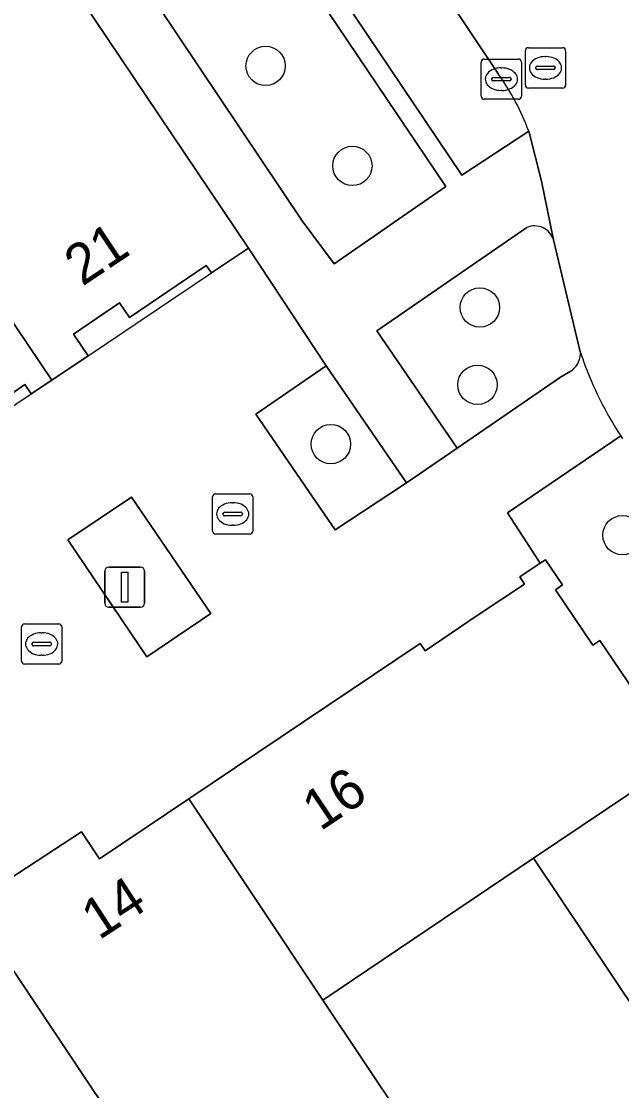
# Model space of a CAD drawing. Extents: x 158793 to 159888, y 384317 to 385256.
# Drawn here: x 159132.82 to 159147.74, y 384807.77 to 384834.32 of the extents above; entities that cross this region are included whole.
import ezdxf

# ---------------------------------------------------------------- set-up
doc = ezdxf.new("R2010")
doc.units = 0
for name, color, linetype in [('IMGEO_Boom', 7, 'Continuous'), ('IMGEO_Erf', 7, 'Continuous'), ('IMGEO_Groenvoorziening', 7, 'Continuous'), ('IMGEO_Kolk', 7, 'Continuous'), ('IMGEO_Lichtmast', 7, 'Continuous'), ('IMGEO_Pand', 7, 'Continuous'), ('IMGEO_Pand_nummerreeks', 7, 'Continuous'), ('IMGEO_Pand_overbouw', 7, 'Continuous'), ('IMGEO_Parkeervlak_open', 7, 'Continuous'), ('IMGEO_Rijbaan_lokaal_open', 7, 'Continuous'), ('IMGEO_Rioolput', 7, 'Continuous'), ('IMGEO_Voetpad_open', 7, 'Continuous')]:
    doc.layers.add(name, color=color, linetype=linetype)

msp = doc.modelspace()

# ---------------------------------------------------------------- linework, layer by layer
at = {"layer": 'IMGEO_Boom'}
for centre in [(159138.893, 384833.21), (159141.048, 384830.727), (159144.217, 384827.212), (159144.156, 384825.292), (159140.515, 384823.82), (159147.761, 384821.559)]:
    msp.add_circle(centre, 0.489, dxfattribs=at)
at = {"layer": 'IMGEO_Erf'}
msp.add_lwpolyline([(159152.783, 384802.742), (159145.552, 384813.536), (159140.318, 384810.016), (159142.302, 384807.041)], dxfattribs=at)
at = {"layer": 'IMGEO_Groenvoorziening'}
for points in [[(159137.509, 384838.918), (159134.663, 384837.03), (159139.797, 384829.364), (159140.593, 384828.294), (159143.37, 384830.219)], [(159140.623, 384821.689), (159142.395, 384822.861), (159140.397, 384825.767), (159138.651, 384824.567), (159139.859, 384822.803)], [(159135.556, 384822.504), (159133.976, 384821.445), (159135.939, 384818.54), (159137.533, 384819.611)]]:
    msp.add_lwpolyline(points, close=True, dxfattribs=at)
for points in [[(159145.384, 384829.198), (159141.656, 384826.635), (159143.651, 384823.723), (159146.223, 384825.482), (159146.515, 384825.659)], [(159146.713, 384826.113), (159146.047, 384828.889)], [(159147.762, 384823.956), (159147.717, 384824.025), (159144.902, 384822.115), (159145.269, 384821.55), (159145.717, 384820.861), (159145.851, 384820.95), (159146.271, 384820.323), (159146.093, 384820.203), (159147.02, 384818.826), (159147.199, 384818.944), (159149.203, 384815.99), (159145.552, 384813.536), (159152.783, 384802.742), (159156.787, 384796.766), (159156.976, 384796.89), (159158.254, 384797.753), (159158.435, 384797.871)]]:
    msp.add_lwpolyline(points, dxfattribs=at)
for centre, radius, start, end in [((159145.58, 384828.752), 0.487, 16.3046, 113.7184), ((159146.177, 384826.077), 0.538, 309.0031, 3.8706)]:
    msp.add_arc(centre, radius, start, end, dxfattribs=at)
at = {"layer": 'IMGEO_Kolk'}
for p, q in [((159144.326, 384833.382), (159145.178, 384833.382)), ((159144.251, 384832.456), (159144.251, 384833.308)), ((159144.739, 384833.162), (159144.764, 384833.162)), ((159145.252, 384833.308), (159145.252, 384832.456)), ((159144.51, 384832.876), (159144.51, 384832.888)), ((159144.948, 384832.839), (159144.55, 384832.839)), ((159144.553, 384832.925), (159144.951, 384832.925)), ((159144.994, 384832.888), (159144.994, 384832.876)), ((159144.762, 384832.602), (159144.737, 384832.602)), ((159145.178, 384832.382), (159144.326, 384832.382)), ((159137.573, 384821.658), (159137.573, 384822.51)), ((159137.648, 384822.584), (159138.5, 384822.584)), ((159138.574, 384822.51), (159138.574, 384821.658)), ((159138.061, 384822.364), (159138.086, 384822.364)), ((159137.832, 384822.078), (159137.832, 384822.09)), ((159138.27, 384822.041), (159137.872, 384822.041)), ((159137.875, 384822.127), (159138.273, 384822.127)), ((159138.316, 384822.09), (159138.316, 384822.078)), ((159138.084, 384821.804), (159138.059, 384821.804)), ((159138.5, 384821.584), (159137.648, 384821.584)), ((159132.901, 384819.356), (159133.753, 384819.356)), ((159132.826, 384818.43), (159132.826, 384819.282)), ((159133.314, 384819.136), (159133.339, 384819.136)), ((159133.827, 384819.282), (159133.827, 384818.43)), ((159133.085, 384818.85), (159133.085, 384818.862)), ((159133.523, 384818.813), (159133.125, 384818.813)), ((159133.128, 384818.899), (159133.526, 384818.899)), ((159133.569, 384818.862), (159133.569, 384818.85)), ((159133.337, 384818.576), (159133.312, 384818.576)), ((159133.753, 384818.356), (159132.901, 384818.356))]:
    msp.add_line(p, q, dxfattribs=at)
for points in [[(159144.326, 384833.382), (159145.178, 384833.382)], [(159144.251, 384832.456), (159144.251, 384833.308)], [(159145.252, 384833.308), (159145.252, 384832.456)], [(159145.178, 384832.382), (159144.326, 384832.382)], [(159137.573, 384821.658), (159137.573, 384822.51)], [(159137.648, 384822.584), (159138.5, 384822.584)], [(159138.574, 384822.51), (159138.574, 384821.658)], [(159138.5, 384821.584), (159137.648, 384821.584)], [(159132.901, 384819.356), (159133.753, 384819.356)], [(159132.826, 384818.43), (159132.826, 384819.282)], [(159133.827, 384819.282), (159133.827, 384818.43)], [(159133.753, 384818.356), (159132.901, 384818.356)]]:
    msp.add_lwpolyline(points, dxfattribs=at)
for centre, radius, start, end in [((159144.328, 384833.306), 0.0765, 91.552, 178.448), ((159144.328, 384833.306), 0.0765, 91.552, 178.448), ((159145.176, 384833.306), 0.0765, 1.552, 88.448), ((159145.176, 384833.306), 0.0765, 1.552, 88.448), ((159144.55, 384832.885), 0.0403, 85.8775, 175.7526), ((159144.547, 384832.875), 0.0366, 178.938, 274.7102), ((159144.951, 384832.882), 0.043, 264.8664, 352.4533), ((159144.955, 384832.887), 0.0386, 1.7309, 96.639), ((159144.328, 384832.458), 0.0765, 181.552, 268.448), ((159144.328, 384832.458), 0.0765, 181.552, 268.448), ((159145.176, 384832.458), 0.0765, 271.552, 358.448), ((159145.176, 384832.458), 0.0765, 271.552, 358.448), ((159137.65, 384822.508), 0.0765, 91.552, 178.448), ((159137.65, 384822.508), 0.0765, 91.552, 178.448), ((159138.498, 384822.508), 0.0765, 1.552, 88.448), ((159138.498, 384822.508), 0.0765, 1.552, 88.448), ((159137.872, 384822.087), 0.0403, 85.8775, 175.7526), ((159137.869, 384822.077), 0.0366, 178.938, 274.7102), ((159138.273, 384822.084), 0.043, 264.8664, 352.4533), ((159138.277, 384822.089), 0.0386, 1.7309, 96.639), ((159137.65, 384821.66), 0.0765, 181.552, 268.448), ((159137.65, 384821.66), 0.0765, 181.552, 268.448), ((159138.498, 384821.66), 0.0765, 271.552, 358.448), ((159138.498, 384821.66), 0.0765, 271.552, 358.448), ((159132.903, 384819.28), 0.0765, 91.552, 178.448), ((159132.903, 384819.28), 0.0765, 91.552, 178.448), ((159133.751, 384819.28), 0.0765, 1.552, 88.448), ((159133.751, 384819.28), 0.0765, 1.552, 88.448), ((159133.125, 384818.859), 0.0403, 85.8775, 175.7526), ((159133.122, 384818.849), 0.0366, 178.938, 274.7102), ((159133.526, 384818.856), 0.043, 264.8664, 352.4533), ((159133.53, 384818.861), 0.0386, 1.7309, 96.639), ((159132.903, 384818.432), 0.0765, 181.552, 268.448), ((159132.903, 384818.432), 0.0765, 181.552, 268.448), ((159133.751, 384818.432), 0.0765, 271.552, 358.448), ((159133.751, 384818.432), 0.0765, 271.552, 358.448)]:
    msp.add_arc(centre, radius, start, end, dxfattribs=at)
for centre, major_axis, ratio, start_param, end_param in [((159144.738, 384832.882), (-0.387, 0.002), 0.722429, 4.712389, 7.853982), ((159144.763, 384832.882), (-0.39, 0.002), 0.717154, 1.570796, 4.712389), ((159138.06, 384822.084), (-0.387, 0.002), 0.722429, 4.712389, 7.853982), ((159138.085, 384822.084), (-0.39, 0.002), 0.717154, 1.570796, 4.712389), ((159133.313, 384818.856), (-0.387, 0.002), 0.722429, 4.712389, 7.853982), ((159133.338, 384818.856), (-0.39, 0.002), 0.717154, 1.570796, 4.712389)]:
    msp.add_ellipse(centre, major_axis=major_axis, ratio=ratio, start_param=start_param, end_param=end_param, dxfattribs=at)
at = {"layer": 'IMGEO_Lichtmast'}
for p, q in [((159134.895, 384819.868), (159134.895, 384820.668)), ((159134.895, 384820.668), (159134.895, 384819.868)), ((159134.995, 384820.768), (159135.785, 384820.768)), ((159135.785, 384820.768), (159134.995, 384820.768)), ((159135.885, 384820.668), (159135.885, 384819.868)), ((159135.885, 384819.868), (159135.885, 384820.668)), ((159135.785, 384819.768), (159134.995, 384819.768)), ((159134.995, 384819.768), (159135.785, 384819.768))]:
    msp.add_line(p, q, dxfattribs=at)
msp.add_lwpolyline([(159135.315, 384820.643), (159135.465, 384820.643), (159135.465, 384819.893), (159135.315, 384819.893), (159135.315, 384820.643)], dxfattribs=at)
for centre, start, end in [((159134.995, 384820.668), 90, 180), ((159134.995, 384820.668), 90, 180), ((159135.785, 384820.668), 0, 90), ((159135.785, 384820.668), 360, 90), ((159134.995, 384819.868), 180, 270), ((159134.995, 384819.868), 180, 270), ((159135.785, 384819.868), 270, 0), ((159135.785, 384819.868), 270, 0)]:
    msp.add_arc(centre, 0.1, start, end, dxfattribs=at)
at = {"layer": 'IMGEO_Pand'}
for points in [[(159132.426, 384837.666), (159127.542, 384834.383), (159128.207, 384833.381), (159133.576, 384825.406), (159134.485, 384826.016), (159134.121, 384826.552), (159135.262, 384827.327), (159135.51, 384826.964), (159137.416, 384828.259), (159137.546, 384828.069), (159138.469, 384828.688)], [(159128.207, 384833.381), (159123.937, 384830.511), (159129.297, 384822.537), (159130.01, 384823.015), (159129.634, 384823.557), (159130.765, 384824.343), (159131.017, 384823.981), (159132.91, 384825.296), (159133.07, 384825.067), (159133.576, 384825.406)], [(159149.203, 384815.99), (159147.199, 384818.944), (159147.02, 384818.826), (159146.093, 384820.203), (159146.271, 384820.323), (159145.851, 384820.95), (159145.717, 384820.861), (159145.208, 384820.523), (159145.325, 384820.346), (159144.149, 384819.56), (159142.856, 384818.69), (159142.735, 384818.868), (159136.984, 384815.015), (159140.318, 384810.016), (159145.552, 384813.536)], [(159140.318, 384810.016), (159136.984, 384815.015), (159134.761, 384813.525), (159134.316, 384814.19), (159132.034, 384812.702), (159132.525, 384812.031), (159131.997, 384811.679), (159137.346, 384803.672), (159142.302, 384807.041)], [(159131.997, 384811.679), (159129.799, 384810.21), (159129.321, 384810.876), (159127.067, 384809.369), (159127.527, 384808.693), (159126.805, 384808.21), (159132.819, 384799.222), (159138.002, 384802.69), (159137.346, 384803.672)]]:
    msp.add_lwpolyline(points, close=True, dxfattribs=at)
at = {"layer": 'IMGEO_Pand_overbouw'}
for points in [[(159137.416, 384828.259), (159135.51, 384826.964), (159135.262, 384827.327), (159134.121, 384826.552), (159134.485, 384826.016), (159137.546, 384828.069)], [(159132.91, 384825.296), (159131.017, 384823.981), (159130.765, 384824.343), (159129.634, 384823.557), (159130.01, 384823.015), (159133.07, 384825.067)]]:
    msp.add_lwpolyline(points, close=True, dxfattribs=at)
at = {"layer": 'IMGEO_Parkeervlak_open'}
for points in [[(159144.677, 384833.004), (159133.178, 384850.193)], [(159133.059, 384849.561), (159131.607, 384848.549), (159143.771, 384830.497), (159145.43, 384831.589)]]:
    msp.add_lwpolyline(points, dxfattribs=at)
msp.add_arc((159139.892, 384829.55), 5.902, 20.2154, 35.8244, dxfattribs=at)
at = {"layer": 'IMGEO_Rijbaan_lokaal_open'}
for points in [[(159112.267, 384881.254), (159112.297, 384881.21), (159125.401, 384861.714), (159133.178, 384850.193), (159144.677, 384833.004)], [(159145.43, 384831.589), (159145.748, 384830.352), (159146.047, 384828.889), (159146.713, 384826.113)], [(159147.717, 384824.025), (159147.762, 384823.956)]]:
    msp.add_lwpolyline(points, dxfattribs=at)
for centre, radius, start, end in [((159139.892, 384829.55), 5.902, 20.2154, 35.8244), ((159153.227, 384828.219), 6.846, 197.9189, 199.9807), ((159155.217, 384828.919), 8.956, 199.8343, 213.1227)]:
    msp.add_arc(centre, radius, start, end, dxfattribs=at)
at = {"layer": 'IMGEO_Rioolput'}
for p, q in [((159145.422, 384833.662), (159146.274, 384833.662)), ((159145.347, 384832.736), (159145.347, 384833.588)), ((159145.835, 384833.442), (159145.86, 384833.442)), ((159146.348, 384833.588), (159146.348, 384832.736)), ((159145.606, 384833.156), (159145.606, 384833.168)), ((159146.044, 384833.119), (159145.646, 384833.119)), ((159145.649, 384833.205), (159146.047, 384833.205)), ((159146.09, 384833.168), (159146.09, 384833.156)), ((159145.858, 384832.882), (159145.833, 384832.882)), ((159146.274, 384832.662), (159145.422, 384832.662))]:
    msp.add_line(p, q, dxfattribs=at)
for points in [[(159145.422, 384833.662), (159146.274, 384833.662)], [(159145.347, 384832.736), (159145.347, 384833.588)], [(159146.348, 384833.588), (159146.348, 384832.736)], [(159146.274, 384832.662), (159145.422, 384832.662)]]:
    msp.add_lwpolyline(points, dxfattribs=at)
for centre, radius, start, end in [((159145.424, 384833.586), 0.0765, 91.552, 178.448), ((159145.424, 384833.586), 0.0765, 91.552, 178.448), ((159146.272, 384833.586), 0.0765, 1.552, 88.448), ((159146.272, 384833.586), 0.0765, 1.552, 88.448), ((159145.646, 384833.165), 0.0403, 85.8775, 175.7526), ((159145.643, 384833.155), 0.0366, 178.938, 274.7102), ((159146.047, 384833.162), 0.043, 264.8664, 352.4533), ((159146.051, 384833.167), 0.0386, 1.7309, 96.639), ((159145.424, 384832.738), 0.0765, 181.552, 268.448), ((159145.424, 384832.738), 0.0765, 181.552, 268.448), ((159146.272, 384832.738), 0.0765, 271.552, 358.448), ((159146.272, 384832.738), 0.0765, 271.552, 358.448)]:
    msp.add_arc(centre, radius, start, end, dxfattribs=at)
for centre, major_axis, ratio, start_param, end_param in [((159145.834, 384833.162), (-0.387, 0.002), 0.722429, 4.712389, 7.853982), ((159145.859, 384833.162), (-0.39, 0.002), 0.717154, 1.570796, 4.712389)]:
    msp.add_ellipse(centre, major_axis=major_axis, ratio=ratio, start_param=start_param, end_param=end_param, dxfattribs=at)
at = {"layer": 'IMGEO_Voetpad_open'}
for points in [[(159131.607, 384848.549), (159131.464, 384848.516), (159131.178, 384848.335), (159136.939, 384839.685), (159134.112, 384837.817), (159125.828, 384850.069), (159124.629, 384849.25), (159124.803, 384848.991), (159128.177, 384843.979), (159128.473, 384843.539), (159132.426, 384837.666), (159138.469, 384828.688), (159140.397, 384825.767), (159142.395, 384822.861), (159143.651, 384823.723), (159141.656, 384826.635), (159145.384, 384829.198)], [(159146.047, 384828.889), (159145.748, 384830.352), (159145.43, 384831.589), (159143.771, 384830.497), (159131.607, 384848.549)], [(159146.515, 384825.659), (159146.223, 384825.482), (159143.651, 384823.723), (159142.395, 384822.861), (159140.623, 384821.689), (159139.859, 384822.803), (159138.651, 384824.567), (159140.397, 384825.767), (159138.469, 384828.688), (159137.546, 384828.069), (159137.416, 384828.259), (159135.51, 384826.964), (159135.262, 384827.327), (159134.121, 384826.552), (159134.485, 384826.016), (159133.576, 384825.406), (159133.07, 384825.067), (159132.91, 384825.296), (159131.017, 384823.981)], [(159134.316, 384814.19), (159134.761, 384813.525), (159136.984, 384815.015), (159142.735, 384818.868), (159142.856, 384818.69), (159144.149, 384819.56), (159145.325, 384820.346), (159145.208, 384820.523), (159145.717, 384820.861), (159145.269, 384821.55), (159144.902, 384822.115), (159147.717, 384824.025)], [(159124.782, 384806.858), (159126.805, 384808.21), (159127.527, 384808.693), (159127.067, 384809.369), (159129.321, 384810.876), (159129.799, 384810.21), (159131.997, 384811.679), (159132.525, 384812.031), (159132.034, 384812.702), (159134.316, 384814.19)]]:
    msp.add_lwpolyline(points, dxfattribs=at)
for points in [[(159137.509, 384838.918), (159143.37, 384830.219), (159140.593, 384828.294), (159139.797, 384829.364), (159134.663, 384837.03)], [(159133.976, 384821.445), (159135.556, 384822.504), (159137.533, 384819.611), (159135.939, 384818.54)]]:
    msp.add_lwpolyline(points, close=True, dxfattribs=at)
for centre, radius, start, end in [((159145.58, 384828.752), 0.487, 16.3046, 113.7184), ((159146.177, 384826.077), 0.538, 309.0031, 3.8706), ((159153.227, 384828.219), 6.846, 197.9189, 199.9807), ((159155.217, 384828.919), 8.956, 199.8343, 213.1227)]:
    msp.add_arc(centre, radius, start, end, dxfattribs=at)

# ---------------------------------------------------------------- texts
at = {"layer": 'IMGEO_Pand_nummerreeks'}
for s, rotation, p in [('21', 33.8446, (159134.338, 384827.725)), ('16', 33.8217, (159140.25, 384814.194)), ('14', 33.1055, (159134.75, 384811.489))]:
    msp.add_text(s, height=1, rotation=rotation, dxfattribs=at).set_placement(p)

doc.saveas('drawing.dxf')
